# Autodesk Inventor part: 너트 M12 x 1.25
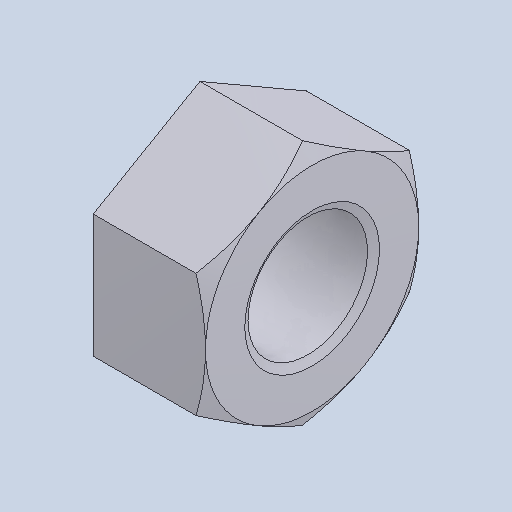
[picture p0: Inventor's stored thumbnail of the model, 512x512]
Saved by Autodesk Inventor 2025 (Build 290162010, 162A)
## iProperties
Created: 2024-08
Part Number: 너트 M12 x 1.25
Material: 스테인리스강
Description: 6각 너트
Document SubType Name: Modeling
Designer: 학생
Density: 8.08 g/cm^3
Appearance: 기본값
Author: jhkim
Sending System: Autodesk Inventor 2025
Preprocessor: ST-DEVELOPER v20
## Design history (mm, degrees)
feature "Solid1"
node "솔리드1"
